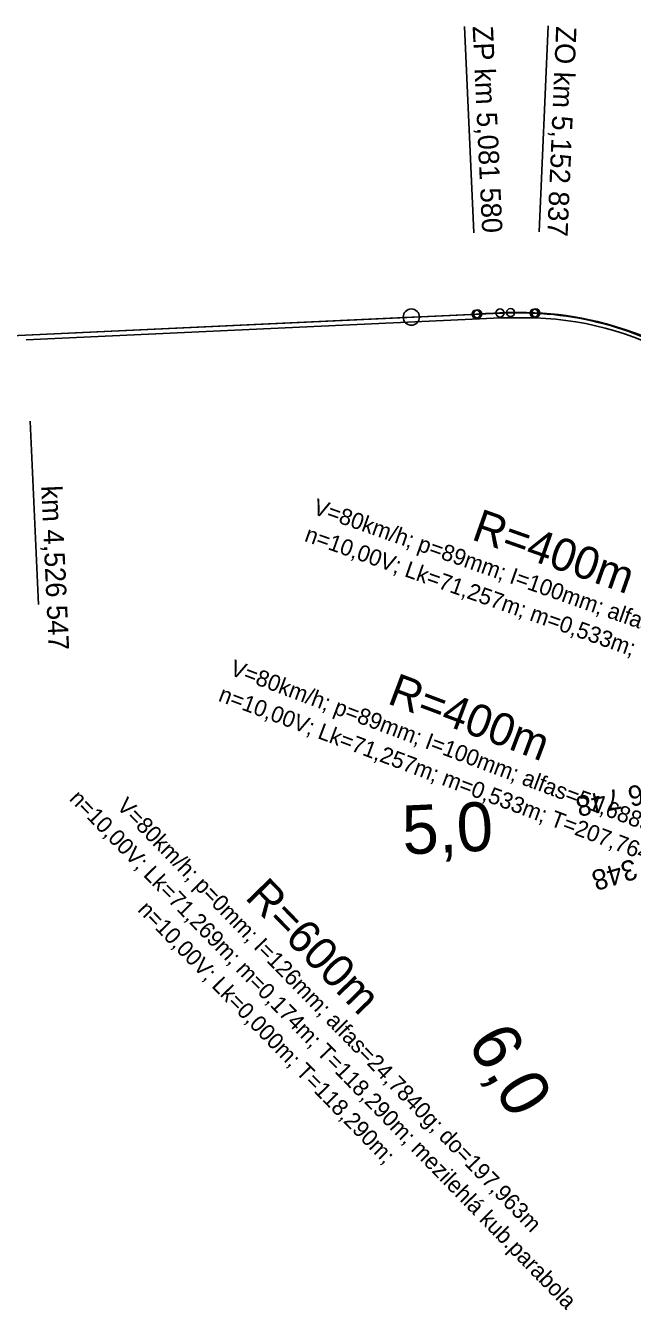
# Model space of a CAD drawing. Extents: x -504999 to -493096, y -1330712 to -1305226.
# Drawn here: x -503678 to -502934, y -1330078 to -1328500 of the extents above; entities that cross this region are included whole.
import ezdxf

# ---------------------------------------------------------------- set-up
doc = ezdxf.new("R2010")
doc.units = 0
for name, color, linetype in [('0_HM', 7, 'Continuous'), ('0_NAVRH V_60_povodnej osi', 7, 'Continuous'), ('0_obluky', 7, 'Continuous'), ('0_popis oblukov', 7, 'Continuous'), ('0_stanicenie oblukov', 7, 'Continuous'), ('0_SUčASNA KOLAJ', 7, 'Continuous'), ('Level 1', 7, 'Continuous'), ('PHS', 7, 'Continuous')]:
    doc.layers.add(name, color=color, linetype=linetype)

msp = doc.modelspace()

# ---------------------------------------------------------------- linework, layer by layer
at = {"layer": '0_HM'}
msp.add_circle((-503205.1, -1328858), 10, dxfattribs=at)
at = {"layer": '0_NAVRH V_60_povodnej osi'}
msp.add_lwpolyline([(-503125.6, -1328854.3), (-503124.6, -1328854.3), (-503123.6, -1328854.2), (-503122.6, -1328854.2), (-503121.6, -1328854.1), (-503120.6, -1328854.1), (-503119.6, -1328854), (-503118.6, -1328854), (-503117.6, -1328853.9), (-503116.6, -1328853.9), (-503115.6, -1328853.8), (-503114.6, -1328853.8), (-503113.6, -1328853.8), (-503112.6, -1328853.7), (-503111.6, -1328853.7), (-503110.6, -1328853.6), (-503109.6, -1328853.6), (-503108.6, -1328853.5), (-503107.6, -1328853.5), (-503106.6, -1328853.5), (-503105.6, -1328853.4), (-503104.6, -1328853.4), (-503103.5, -1328853.3), (-503102.5, -1328853.3), (-503101.5, -1328853.3), (-503100.5, -1328853.2), (-503099.5, -1328853.2), (-503098.5, -1328853.2), (-503097.5, -1328853.1), (-503096.5, -1328853.1), (-503095.5, -1328853.1), (-503094.5, -1328853), (-503093.5, -1328853), (-503092.5, -1328853), (-503091.5, -1328853), (-503090.5, -1328852.9), (-503089.5, -1328852.9), (-503088.5, -1328852.9), (-503087.5, -1328852.9), (-503086.5, -1328852.8), (-503085.5, -1328852.8), (-503084.5, -1328852.8), (-503083.5, -1328852.8), (-503082.5, -1328852.8), (-503081.5, -1328852.8), (-503080.5, -1328852.7), (-503079.5, -1328852.7), (-503078.5, -1328852.7), (-503077.5, -1328852.7), (-503076.5, -1328852.7), (-503075.5, -1328852.7), (-503074.5, -1328852.7), (-503073.5, -1328852.7), (-503072.5, -1328852.7), (-503071.5, -1328852.7), (-503070.4, -1328852.7), (-503069.4, -1328852.7), (-503068.4, -1328852.7), (-503067.4, -1328852.8), (-503066.4, -1328852.8), (-503065.4, -1328852.8), (-503064.4, -1328852.8), (-503063.4, -1328852.8), (-503062.4, -1328852.9), (-503061.4, -1328852.9), (-503060.4, -1328852.9), (-503059.4, -1328852.9), (-503058.4, -1328853), (-503057.4, -1328853), (-503056.4, -1328853), (-503055.4, -1328853.1), (-503054.4, -1328853.1)], dxfattribs=at)
for centre in [(-503125.6, -1328854.3), (-503054.4, -1328853.1)]:
    msp.add_circle(centre, 5, dxfattribs=at)
msp.add_arc((-503071.5, -1329252.8), 400, 51.2431, 87.5506, dxfattribs=at)
at = {"layer": '0_obluky'}
msp.add_line((-504065.8, -1328897.9), (-503123.6, -1328854.2), dxfattribs=at)
msp.add_lwpolyline([(-503123.6, -1328854.2), (-503122.6, -1328854.2), (-503121.6, -1328854.1), (-503120.6, -1328854.1), (-503119.6, -1328854), (-503118.6, -1328854), (-503117.6, -1328853.9), (-503116.6, -1328853.9), (-503115.5, -1328853.8), (-503114.5, -1328853.8), (-503113.5, -1328853.7), (-503112.5, -1328853.7), (-503111.5, -1328853.7), (-503110.5, -1328853.6), (-503109.5, -1328853.6), (-503108.5, -1328853.5), (-503107.5, -1328853.5), (-503106.5, -1328853.4), (-503105.5, -1328853.4), (-503104.5, -1328853.4), (-503103.5, -1328853.3), (-503102.5, -1328853.3), (-503101.5, -1328853.2), (-503100.5, -1328853.2), (-503099.5, -1328853.2), (-503098.5, -1328853.1), (-503097.5, -1328853.1), (-503096.5, -1328853.1), (-503095.5, -1328853), (-503094.5, -1328853), (-503093.5, -1328853), (-503092.5, -1328852.9), (-503091.5, -1328852.9), (-503090.5, -1328852.9), (-503089.5, -1328852.9), (-503088.5, -1328852.8), (-503087.5, -1328852.8), (-503086.5, -1328852.8), (-503085.5, -1328852.8), (-503084.5, -1328852.7), (-503083.5, -1328852.7), (-503082.5, -1328852.7), (-503081.5, -1328852.7), (-503080.5, -1328852.7), (-503079.5, -1328852.7), (-503078.5, -1328852.7), (-503077.5, -1328852.6), (-503076.5, -1328852.6), (-503075.5, -1328852.6), (-503074.4, -1328852.6), (-503073.4, -1328852.6), (-503072.4, -1328852.6), (-503071.4, -1328852.6), (-503070.4, -1328852.6), (-503069.4, -1328852.6), (-503068.4, -1328852.6), (-503067.4, -1328852.6), (-503066.4, -1328852.7), (-503065.4, -1328852.7), (-503064.4, -1328852.7), (-503063.4, -1328852.7), (-503062.4, -1328852.7), (-503061.4, -1328852.7), (-503060.4, -1328852.8), (-503059.4, -1328852.8), (-503058.4, -1328852.8), (-503057.4, -1328852.8), (-503056.4, -1328852.9), (-503055.4, -1328852.9), (-503054.4, -1328852.9), (-503053.3, -1328853), (-503052.3, -1328853)], dxfattribs=at)
for centre in [(-503123.6, -1328854.2), (-503052.3, -1328853)]:
    msp.add_circle(centre, 5, dxfattribs=at)
msp.add_arc((-503069.4, -1329252.7), 400, 58.803, 87.5506, dxfattribs=at)
at = {"layer": '0_stanicenie oblukov'}
for p, q in [((-503128.2, -1328754.3), (-503139.9, -1328501.3)), ((-503048.1, -1328753.1), (-503037.2, -1328500.1)), ((-503131, -1328854.6), (-504225, -1328905.3))]:
    msp.add_line(p, q, dxfattribs=at)
at = {"layer": '0_SUčASNA KOLAJ'}
msp.add_lwpolyline([(-503096.3, -1328852.9), (-503095.3, -1328852.9), (-503094.3, -1328852.8), (-503093.3, -1328852.8), (-503092.3, -1328852.8), (-503091.3, -1328852.7), (-503090.3, -1328852.7), (-503089.3, -1328852.6), (-503088.3, -1328852.6), (-503087.3, -1328852.5), (-503086.3, -1328852.5), (-503085.3, -1328852.5), (-503084.3, -1328852.4), (-503083.3, -1328852.4)], dxfattribs=at)
for centre in [(-503096.3, -1328852.9), (-503083.3, -1328852.4)]:
    msp.add_circle(centre, 5, dxfattribs=at)
msp.add_arc((-503071.3, -1329252.2), 400, 47.0681, 91.7257, dxfattribs=at)
at = {"layer": 'Level 1'}
msp.add_line((-503195.9, -1328857.6), (-504117.5, -1328900.3), dxfattribs=at)
at = {"layer": 'PHS'}
for p, q in [((-503677.7, -1328885.9), (-503121.3, -1328860.1)), ((-503673.1, -1328985.8), (-503662.7, -1329210.7))]:
    msp.add_line(p, q, dxfattribs=at)
for centre, radius, start, end in [((-503074.5, -1329643), 784.3, 88.391, 93.4161), ((-503063, -1329231.3), 372.4, 57.9626, 88.391)]:
    msp.add_arc(centre, radius, start, end, dxfattribs=at)

# ---------------------------------------------------------------- texts
at = {"layer": '0_HM'}
for s, rotation, p in [('5,0', 2.6567, (-503215, -1329517.9)), ('6,0', 300.1541, (-503137.2, -1329748.6))]:
    msp.add_text(s, height=60, rotation=rotation, dxfattribs=at).set_placement(p)
at = {"layer": '0_NAVRH V_60_povodnej osi'}
for s, height, p in [('V=80km/h; p=89mm; I=100mm; alfas=51,6885g; do=253,474m', 20, (-503429.1, -1329296.8)), ('R=400m', 40, (-503235.9, -1329332)), ('n=10,00V; Lk=71,257m; m=0,533m; T=207,764m; kub.parabola', 20, (-503443.1, -1329328.9))]:
    msp.add_text(s, height=height, rotation=339.3969, dxfattribs=at).set_placement(p)
at = {"layer": '0_obluky'}
for s, height, p in [('V=80km/h; p=89mm; I=100mm; alfas=43,2887g; do=200,697m', 20, (-503327.1, -1329099.2)), ('R=400m', 40, (-503132.6, -1329130.6)), ('n=10,00V; Lk=71,257m; m=0,533m; T=176,707m; kub.parabola', 20, (-503337.4, -1329132.7))]:
    msp.add_text(s, height=height, rotation=340.5997, dxfattribs=at).set_placement(p)
at = {"layer": '0_popis oblukov'}
for s, height, p in [('n=10,00V; Lk=71,269m; m=0,174m; T=118,290m; mezilehlá kub.parabola', 20, (-503625.9, -1329450.4)), ('V=80km/h; p=0mm; I=126mm; alfas=24,7840g; do=197,963m', 20, (-503567.8, -1329459.8)), ('R=600m', 40, (-503410.3, -1329571.4)), ('n=10,00V; Lk=0,000m; T=118,290m;', 20, (-503542, -1329586.7))]:
    msp.add_text(s, height=height, rotation=314.2518, dxfattribs=at).set_placement(p)
at = {"layer": '0_stanicenie oblukov'}
for s, rotation, p in [('ZP km 5,081 580', 272.6567, (-503129.9, -1328500.9)), ('ZO km 5,152 837', 267.5506, (-503027.3, -1328500.5)), ('ZP km 5,896 748', 190.9046, (-502754.9, -1329399)), ('ZO km 5,945 348', 196.8292, (-502738.6, -1329464.2))]:
    msp.add_text(s, height=25, rotation=rotation, dxfattribs=at).set_placement(p)
at = {"layer": 'PHS'}
msp.add_text('km 4,526 547', height=25, rotation=272.6567, dxfattribs=at).set_placement((-503659.4, -1329065.3))

doc.saveas('drawing.dxf')
